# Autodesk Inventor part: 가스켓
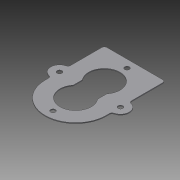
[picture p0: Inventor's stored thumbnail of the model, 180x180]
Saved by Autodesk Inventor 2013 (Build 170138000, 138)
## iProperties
Created: 2024-02
Part Number: 가스켓
Material: 스테인리스강
Document SubType Name: Modeling
Designer: mdu-01
Density: 1 g/cm^3
Author: mdu-01
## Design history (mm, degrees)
sketch "스케치1"
  geometry: L1 (35, -4.851)-(35, 46) reference; L2 (35, 46)-(15, 46) reference; L3 (15, 37)-(15, 46) reference; L4 (12, 34)-(-12, 34) reference; L5 (-15, 37)-(-15, 46) reference; L6 (-35, 46)-(-15, 46) reference; L7 (-35, -4.851)-(-35, 46) reference; L8 (-35, -34)-(-35, -30.149) reference; L9 (35, -34)-(35, -30.149) reference; L10 (-14, -22.686)-(-14, -12.314) reference; L11 (14, -12.314)-(14, -22.686) reference; L12 (-35, -4.851)-(-35, 31); L13 (-32, 34)-(32, 34); L14 (35, 31)-(35, -4.851); C1 r 10 at (0, -1) reference; C2 r 10 at (0, -34) reference; C3 r 2.067 at (-35, -17.5) reference; C4 r 2.067 at (0, 25) reference; C5 r 2.067 at (0, -60) reference; C6 r 2.067 at (35, -17.5) reference; C7 r 2.75 at (0, 25); C8 r 2.75 at (35, -17.5); C9 r 2.75 at (-35, -17.5); C10 r 2.75 at (0, -60); A1 r 3 centre (12, 37) between (12, 34) and (15, 37) reference; A2 r 3 centre (-12, 37) between (-15, 37) and (-12, 34) reference; A3 r 3 centre (-38, -4.851) between (-37.308, -7.77) and (-35, -4.851) reference; A4 r 10 centre (-35, -17.5) between (-37.308, -7.77) and (-37.308, -27.23) reference; A5 r 3 centre (-38, -30.149) between (-35, -30.149) and (-37.308, -27.23) reference; A6 r 35 centre (0, -34) between (-35, -34) and (35, -34) reference; A7 r 3 centre (38, -30.149) between (37.308, -27.23) and (35, -30.149) reference; A8 r 10 centre (35, -17.5) between (37.308, -27.23) and (37.308, -7.77) reference; A9 r 3 centre (38, -4.851) between (35, -4.851) and (37.308, -7.77) reference; A10 r 18 centre (0, -1) between (14, -12.314) and (-14, -12.314) reference; A11 r 18 centre (0, -34) between (-14, -22.686) and (14, -22.686) reference; A12 r 3 centre (-32, 31) between (-32, 34) and (-35, 31); A13 r 3 centre (32, 31) between (35, 31) and (32, 34); 3 further points
  constraints: 6 centre point, 6 end point, 6 point on line, 6 tangent, 4 coincident, 4 equal radius, 4 point on circle, 2 collinear, 1 perpendicular
  dimensions: "d0" = 3 radius of A12; "d1" = 5.5 diameter of C7
extrude "돌출1" new body sketch "스케치1" distance "d2" = 1; taper "d3" = 0 deg
node "솔리드1"
node "참조1"
node "참조2"
node "참조3"
